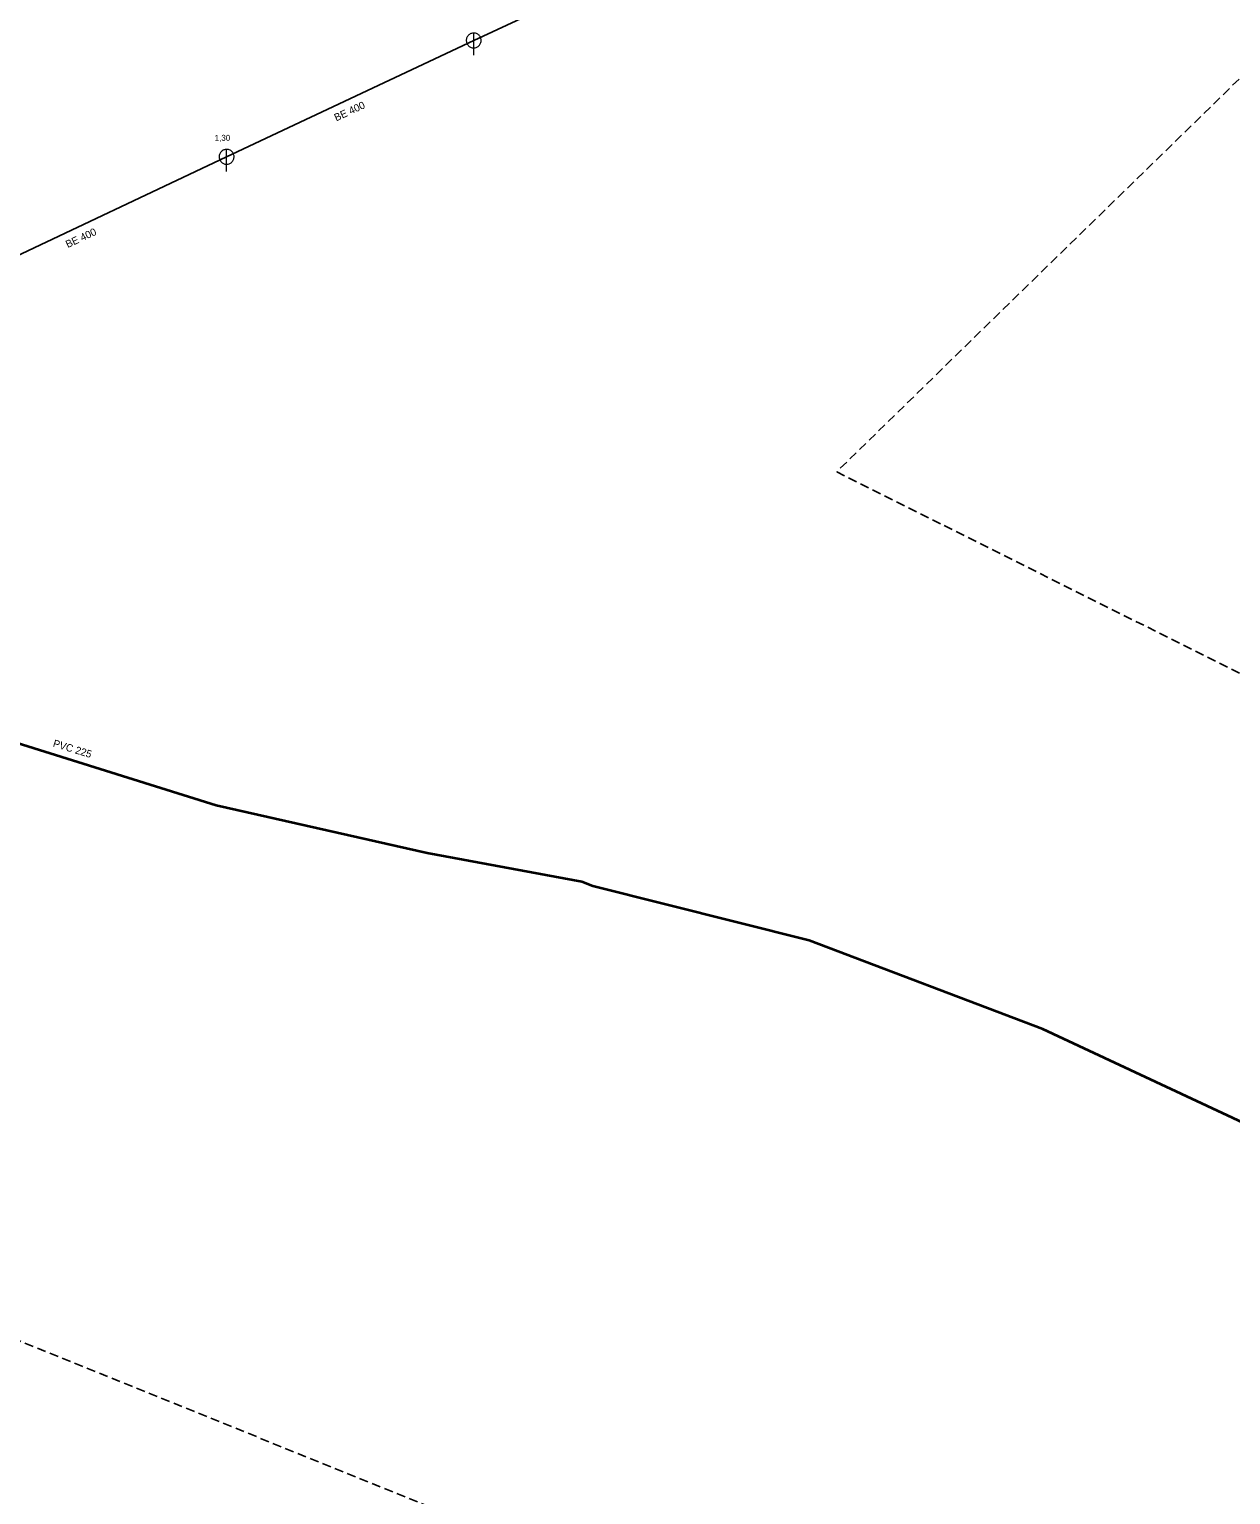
# Model space of a CAD drawing. Extents: x -724334 to -723692, y -972150 to -970648.
# Drawn here: x -724174.5 to -724012.8, y -971202 to -971004.7 of the extents above; entities that cross this region are included whole.
import ezdxf

# ---------------------------------------------------------------- set-up
doc = ezdxf.new("R2010")
doc.units = 0
doc.header["$LTSCALE"] = 0.4
doc.linetypes.add('MEDIUM_DASHED', pattern=[4.5, 3, -1.5])
for name, color, linetype, lineweight in [('1', 7, 'Continuous', 25), ('14', 7, 'Continuous', 25), ('17', 7, 'Continuous', 35), ('22', 7, 'Continuous', 13)]:
    doc.layers.add(name, color=color, linetype=linetype, lineweight=lineweight)

msp = doc.modelspace()

# ---------------------------------------------------------------- linework, layer by layer
at = {"layer": '1', "linetype": 'MEDIUM_DASHED'}
msp.add_lwpolyline([(-723848.074, -970648.428), (-723714.095, -970720.999), (-724065.788, -971064.318), (-723792.249, -971201.088), (-723702.93, -971508.122), (-723691.766, -972150.101), (-723842.491, -972097.068), (-723864.821, -971424.385), (-723982.052, -971259.703), (-724333.745, -971117.352)], close=True, dxfattribs=at)
at = {"layer": '14'}
for p, q in [((-724068.879, -970984.93), (-724114.64, -971006.25)), ((-724114.64, -971006.25), (-724147.899, -971021.91)), ((-724147.899, -971021.91), (-724186.94, -971040.35))]:
    msp.add_line(p, q, dxfattribs=at)
at = {"layer": '17'}
msp.add_lwpolyline([(-723856.75, -971277.52), (-723871.469, -971261.379), (-723894.09, -971234.91), (-723915.739, -971210.25), (-723934.449, -971190.379), (-723958.59, -971177.719), (-723983.8, -971165.17), (-724007.629, -971153.55), (-724038.03, -971139.35), (-724069.469, -971127.41), (-724098.62, -971120.079), (-724100.07, -971119.51), (-724120.89, -971115.66), (-724149.294, -971109.225), (-724187.32, -971097.32), (-724220.714, -971087.254)], dxfattribs=at)
at = {"layer": '22'}
for p, q in [((-724114.64, -971008.25), (-724114.639, -971005.25)), ((-724147.899, -971023.91), (-724147.898, -971020.91))]:
    msp.add_line(p, q, dxfattribs=at)
for points in [[(-724113.64, -971006.25), (-724113.645, -971006.141), (-724113.663, -971006.033), (-724113.693, -971005.927), (-724113.733, -971005.826), (-724113.785, -971005.729), (-724113.847, -971005.639), (-724113.919, -971005.556), (-724113.999, -971005.482), (-724114.087, -971005.416), (-724114.181, -971005.361), (-724114.281, -971005.316), (-724114.386, -971005.283), (-724114.493, -971005.261), (-724114.602, -971005.251), (-724114.712, -971005.253), (-724114.82, -971005.267), (-724114.927, -971005.292), (-724115.03, -971005.329), (-724115.128, -971005.378), (-724115.22, -971005.436), (-724115.306, -971005.505), (-724115.383, -971005.582), (-724115.452, -971005.668), (-724115.511, -971005.76), (-724115.559, -971005.858), (-724115.596, -971005.961), (-724115.622, -971006.068), (-724115.636, -971006.176), (-724115.639, -971006.286), (-724115.629, -971006.395), (-724115.608, -971006.502), (-724115.574, -971006.606), (-724115.53, -971006.706), (-724115.475, -971006.801), (-724115.409, -971006.889), (-724115.335, -971006.969), (-724115.252, -971007.041), (-724115.162, -971007.103), (-724115.066, -971007.155), (-724114.964, -971007.196), (-724114.859, -971007.226), (-724114.751, -971007.244), (-724114.641, -971007.25), (-724114.532, -971007.244), (-724114.424, -971007.226), (-724114.319, -971007.197), (-724114.217, -971007.156), (-724114.12, -971007.104), (-724114.03, -971007.042), (-724113.947, -971006.971), (-724113.872, -971006.891), (-724113.807, -971006.803), (-724113.751, -971006.709), (-724113.707, -971006.609), (-724113.673, -971006.505), (-724113.651, -971006.397), (-724113.641, -971006.288)], [(-724146.899, -971021.91), (-724146.904, -971021.801), (-724146.922, -971021.693), (-724146.952, -971021.587), (-724146.992, -971021.486), (-724147.044, -971021.389), (-724147.106, -971021.299), (-724147.178, -971021.216), (-724147.258, -971021.142), (-724147.346, -971021.076), (-724147.44, -971021.021), (-724147.54, -971020.976), (-724147.645, -971020.943), (-724147.752, -971020.921), (-724147.861, -971020.911), (-724147.971, -971020.913), (-724148.079, -971020.927), (-724148.186, -971020.952), (-724148.289, -971020.989), (-724148.387, -971021.038), (-724148.479, -971021.096), (-724148.565, -971021.165), (-724148.642, -971021.242), (-724148.711, -971021.328), (-724148.77, -971021.42), (-724148.818, -971021.518), (-724148.855, -971021.621), (-724148.881, -971021.728), (-724148.895, -971021.836), (-724148.898, -971021.946), (-724148.888, -971022.055), (-724148.867, -971022.162), (-724148.833, -971022.266), (-724148.789, -971022.366), (-724148.734, -971022.461), (-724148.668, -971022.549), (-724148.594, -971022.629), (-724148.511, -971022.701), (-724148.421, -971022.763), (-724148.325, -971022.815), (-724148.223, -971022.856), (-724148.118, -971022.886), (-724148.01, -971022.904), (-724147.9, -971022.91), (-724147.791, -971022.904), (-724147.683, -971022.886), (-724147.578, -971022.857), (-724147.476, -971022.816), (-724147.379, -971022.764), (-724147.289, -971022.702), (-724147.206, -971022.631), (-724147.131, -971022.551), (-724147.066, -971022.463), (-724147.01, -971022.369), (-724146.966, -971022.269), (-724146.932, -971022.165), (-724146.91, -971022.057), (-724146.9, -971021.948)]]:
    msp.add_lwpolyline(points, close=True, dxfattribs=at)

# ---------------------------------------------------------------- texts
at = {"layer": '1'}
for s, rotation, p in [('BE 400', 25, (-724133.138, -971017.153)), ('BE 400', 25, (-724169.284, -971034.205)), ('PVC 225 ', 343, (-724171.352, -971101.286))]:
    msp.add_text(s, height=1, rotation=rotation, dxfattribs=at).set_placement(p)
msp.add_text('1,30', height=0.8, dxfattribs=at).set_placement((-724149.5, -971019.757))

doc.saveas('drawing.dxf')
